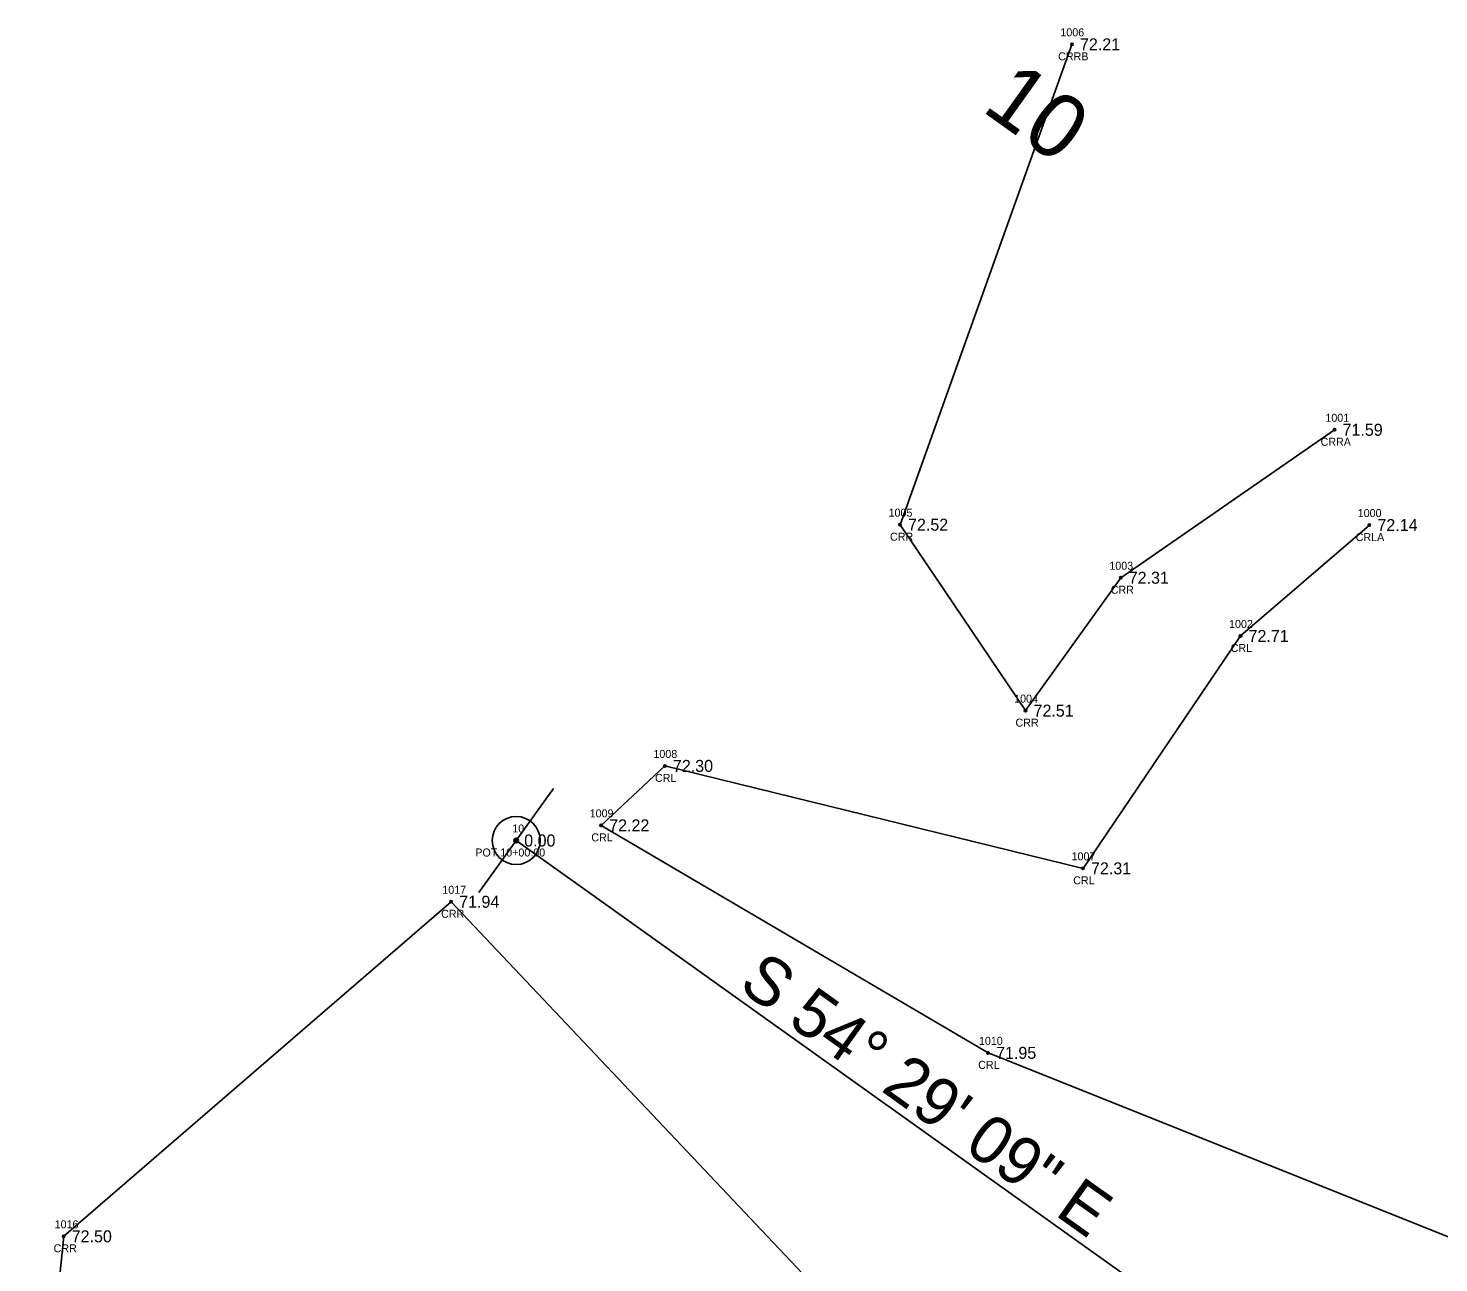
# Model space of a CAD drawing. Extents: x 2505249 to 2506333, y 912937 to 914171.
# Drawn here: x 2505594.6 to 2505770.9, y 913565.9 to 913720.2 of the extents above; entities that cross this region are included whole.
import ezdxf

# ---------------------------------------------------------------- set-up
doc = ezdxf.new("R2010")
doc.units = 0
for name, color, linetype in [('RD_EX_H2O', 7, 'Continuous'), ('RD_EX_H2O_txCode', 7, 'Continuous'), ('RD_EX_TX_H2O_ELEV', 7, 'Continuous'), ('RD_HC_Cl', 7, 'Continuous'), ('RD_HC_Data', 7, 'Continuous'), ('RD_HC_Data_Tic', 7, 'Continuous'), ('RD_HC_Survey_ELEV', 7, 'Continuous'), ('RD_HC_TX_Sta50', 7, 'Continuous'), ('RD_HC_txCode', 7, 'Continuous'), ('RD_SMD_Locator', 7, 'Continuous')]:
    doc.layers.add(name, color=color, linetype=linetype)

msp = doc.modelspace()

# ---------------------------------------------------------------- linework, layer by layer
at = {"layer": 'RD_EX_H2O'}
for points in [[(2505757.9, 913670.02), (2505731.18, 913651.53), (2505719.28, 913634.92), (2505703.6, 913658.16), (2505725.09, 913718.19)], [(2505762.26, 913658.11), (2505746.15, 913644.25), (2505726.47, 913615.21), (2505674.21, 913628.01), (2505666.25, 913620.58), (2505714.6, 913592.15), (2505793.9, 913560.45), (2505801.32, 913552.8), (2505803.7, 913539.77), (2505832.63, 913516.96), (2505848.42, 913517.19), (2505881.86, 913528.44), (2505910.2, 913538.78), (2505939.3, 913544.45), (2505946.25, 913542.54), (2505974.65, 913535.18), (2506004.11, 913524.7), (2506052.03, 913515.47), (2506115.49, 913494.68), (2506138.05, 913548.89)], [(2505594.65, 913525.76), (2505599.08, 913569.22), (2505647.5, 913611.03), (2505694.26, 913561.57), (2505732.63, 913542.98), (2505739.24, 913533.06)]]:
    msp.add_lwpolyline(points, dxfattribs=at)
at = {"layer": 'RD_HC_Cl'}
msp.add_line((2505655.63, 913618.69), (2505757.7, 913545.85), dxfattribs=at)
at = {"layer": 'RD_HC_Data'}
for radius in [3, 0.282]:
    msp.add_circle((2505655.63, 913618.69), radius, dxfattribs=at)
at = {"layer": 'RD_HC_Data_Tic'}
for q in [(2505660.28, 913625.2), (2505650.98, 913612.18)]:
    msp.add_line((2505655.63, 913618.69), q, dxfattribs=at)
at = {"layer": 'RD_SMD_Locator'}
for centre in [(2505725.09, 913718.19), (2505757.9, 913670.02), (2505703.6, 913658.16), (2505762.26, 913658.11), (2505731.18, 913651.53), (2505746.15, 913644.25), (2505719.28, 913634.92), (2505674.21, 913628.01), (2505666.25, 913620.58), (2505655.63, 913618.69), (2505726.47, 913615.21), (2505647.5, 913611.03), (2505714.6, 913592.15), (2505599.08, 913569.22)]:
    msp.add_circle(centre, 0.15, dxfattribs=at)

# ---------------------------------------------------------------- texts
at = {"layer": 'RD_EX_H2O_txCode'}
for s, p in [('1006', (2505723.64, 913719.19)), ('CRRB', (2505723.36, 913716.19)), ('1001', (2505756.76, 913671.02)), ('CRRA', (2505756.16, 913668.02)), ('1005', (2505702.17, 913659.16)), ('1000', (2505760.8, 913659.11)), ('CRR', (2505702.35, 913656.16)), ('CRLA', (2505760.55, 913656.11)), ('1003', (2505729.76, 913652.53)), ('CRR', (2505729.93, 913649.53)), ('1002', (2505744.72, 913645.25)), ('CRL', (2505744.92, 913642.25)), ('1004', (2505717.86, 913635.92)), ('CRR', (2505718.03, 913632.92)), ('1008', (2505672.78, 913629.01)), ('CRL', (2505672.98, 913626.01)), ('1009', (2505664.82, 913621.58)), ('CRL', (2505665.02, 913618.58)), ('1007', (2505725.04, 913616.21)), ('CRL', (2505725.24, 913613.21)), ('1017', (2505646.4, 913612.03)), ('CRR', (2505646.25, 913609.03)), ('1010', (2505713.46, 913593.15)), ('CRL', (2505713.37, 913590.15)), ('1016', (2505597.95, 913570.22)), ('CRR', (2505597.82, 913567.22))]:
    msp.add_text(s, height=1, dxfattribs=at).set_placement(p)
at = {"layer": 'RD_EX_TX_H2O_ELEV'}
for s, p in [('72.21', (2505726.09, 913717.44)), ('71.59', (2505758.9, 913669.27)), ('72.52', (2505704.6, 913657.41)), ('72.14', (2505763.26, 913657.36)), ('72.31', (2505732.18, 913650.78)), ('72.71', (2505747.15, 913643.5)), ('72.51', (2505720.28, 913634.17)), ('72.30', (2505675.21, 913627.26)), ('72.22', (2505667.25, 913619.83)), ('72.31', (2505727.47, 913614.46)), ('71.94', (2505648.5, 913610.28)), ('71.95', (2505715.6, 913591.4)), ('72.50', (2505600.08, 913568.47))]:
    msp.add_text(s, height=1.5, dxfattribs=at).set_placement(p)
at = {"layer": 'RD_HC_Data'}
msp.add_text('S 54%%d 29\' 09" E', height=6, rotation=324.4859, dxfattribs=at).set_placement((2505683.23, 913600.22))
at = {"layer": 'RD_HC_Survey_ELEV'}
msp.add_text('0.00', height=1.5, dxfattribs=at).set_placement((2505656.63, 913617.94))
at = {"layer": 'RD_HC_TX_Sta50'}
msp.add_text('10', height=8, rotation=324.4859, dxfattribs=at).set_placement((2505713.65, 913709.97))
at = {"layer": 'RD_HC_txCode'}
for s, p in [('10', (2505655.14, 913619.69)), ('POT 10+00.00', (2505650.52, 913616.69))]:
    msp.add_text(s, height=1, dxfattribs=at).set_placement(p)

doc.saveas('drawing.dxf')
